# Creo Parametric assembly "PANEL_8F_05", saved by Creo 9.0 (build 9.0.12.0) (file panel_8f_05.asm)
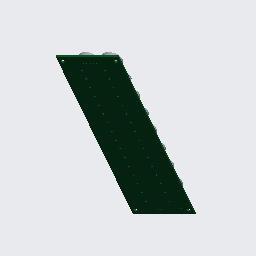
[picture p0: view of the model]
Units: millimeter Newton Second (mmNs); MM, TONNE, SECS

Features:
  1. coordinate system "PANEL_8F_05"
  2. imported feature "Import Feature id 4"
  3. component "PCB_8F"
  4. component "TX_8F_T1"
  5. component "TX_8F_T1"
  6. component "TX_8F_T1"
  7. component "TX_8F_T1"
  8. component "TX_8F_T1"
  9. component "TX_8F_T1"
  10. component "TX_8F_T1"
  11. component "TX_8F_T1"
  12. component "TX_8F_T1"
  13. component "TX_8F_T1"
  14. component "TX_8F_T1"
  15. component "TX_8F_T1"
  16. component "TX_8F_T1"
  17. component "TX_8F_T1"
  18. component "TX_8F_T1"
  19. component "TX_8F_T1"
